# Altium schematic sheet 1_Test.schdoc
size 431 x 309 mm; Symbol: Sheet-Symbol_A3; Device: Sheet-Symbol_A3; Company: 嘉立创EDA; Version: V1.0; Page Size: A3; @Project Name: 辉光管_2024.2.16; @Page Count: 1; @Update Date: 2024-07-01; @Create Date: 2024-04-11; @Schematic Name: Schematic2; @Page No: 1; @Page Name: Test
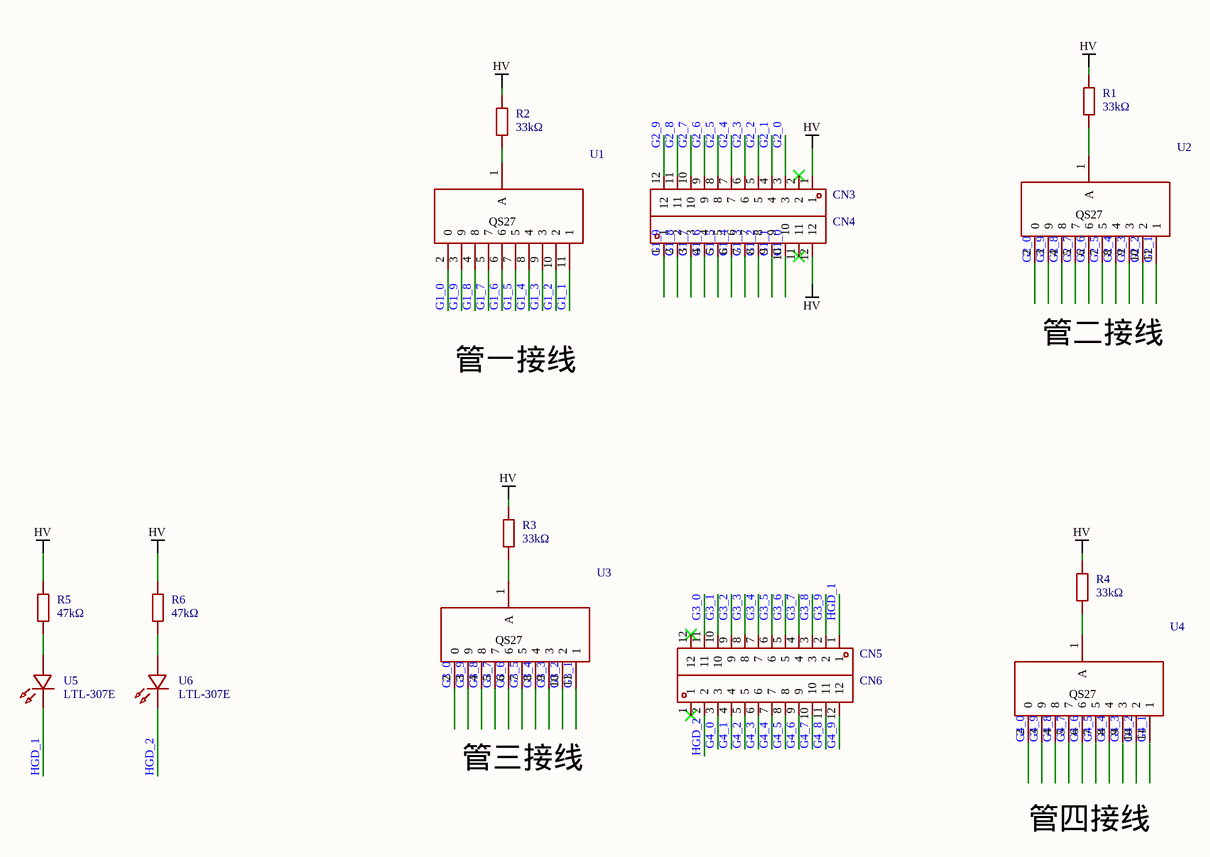
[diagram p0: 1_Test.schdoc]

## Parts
CN3  HB-PH3-254112PB2GOP  [HDR-TH_12P-P2.54-V-M]  (value not drawn)
CN4  HB-PH3-254112PB2GOP  [HDR-TH_12P-P2.54-V-M]  (value not drawn)
CN5  HB-PH3-254112PB2GOP  [HDR-TH_12P-P2.54-V-M]  (value not drawn)
CN6  HB-PH3-254112PB2GOP  [HDR-TH_12P-P2.54-V-M]  (value not drawn)
R1  33kΩ  [R0805]  (value not drawn)
R2  33kΩ  [R0805]  (value not drawn)
R3  33kΩ  [R0805]  (value not drawn)
R4  33kΩ  [R0805]  (value not drawn)
R5  47kΩ  [R0805]  (value not drawn)
R6  47kΩ  [R0805]  (value not drawn)
U1  QS27.1  [QS27]  (value not drawn)
U2  QS27.1  [QS27]  (value not drawn)
U3  QS27.1  [QS27]  (value not drawn)
U4  QS27.1  [QS27]  (value not drawn)
U5  LTL-307E  [LED-TH_BD5.9-P2.54-RD_RED]  (value not drawn)
U6  LTL-307E  [LED-TH_BD5.9-P2.54-RD_RED]  (value not drawn)

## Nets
HV: CN3.1 CN4.12 R1.2 R2.2 R3.2 R4.2 R5.2 R6.2
G1_0: CN4.10 U1.2(0)
G1_1: CN4.9 U1.11(1)
G1_2: CN4.8 U1.10(2)
G1_3: CN4.7 U1.9(3)
G1_4: CN4.6 U1.8(4)
G1_5: CN4.5 U1.7(5)
G1_6: CN4.4 U1.6
G1_7: CN4.3 U1.5(7)
G1_8: CN4.2 U1.4(8)
G1_9: CN4.1 U1.3(9)
G2_0: CN3.3 U2.2(0)
G2_1: CN3.4 U2.11(1)
G2_2: CN3.5 U2.10(2)
G2_3: CN3.6 U2.9(3)
G2_4: CN3.7 U2.8(4)
G2_5: CN3.8 U2.7(5)
G2_6: CN3.9 U2.6
G2_7: CN3.10 U2.5(7)
G2_8: CN3.11 U2.4(8)
G2_9: CN3.12 U2.3(9)
G3_0: CN5.11 U3.2(0)
G3_1: CN5.10 U3.11(1)
G3_2: CN5.9 U3.10(2)
G3_3: CN5.8 U3.9(3)
G3_4: CN5.7 U3.8(4)
G3_5: CN5.6 U3.7(5)
G3_6: CN5.5 U3.6
G3_7: CN5.4 U3.5(7)
G3_8: CN5.3 U3.4(8)
G3_9: CN5.2 U3.3(9)
G4_0: CN6.3 U4.2(0)
G4_1: CN6.4 U4.11(1)
G4_2: CN6.5 U4.10(2)
G4_3: CN6.6 U4.9(3)
G4_4: CN6.7 U4.8(4)
G4_5: CN6.8 U4.7(5)
G4_6: CN6.9 U4.6
G4_7: CN6.10 U4.5(7)
G4_8: CN6.11 U4.4(8)
G4_9: CN6.12 U4.3(9)
HGD_1: CN5.1 U5.1(C)
HGD_2: CN6.2 U6.1(C)
NetR1_1: R1.1 U2.1(A)
NetR2_1: R2.1 U1.1(A)
NetR3_1: R3.1 U3.1(A)
NetR4_1: R4.1 U4.1(A)
NetR5_1: R5.1 U5.2(A)
NetR6_1: R6.1 U6.2(A)

Not connected (* = marked no-connect by the designer): CN3 2*; CN4 11*; CN5 12*; CN6 1*

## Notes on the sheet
- 管二接线
- 管一接线
- 管三接线
- 管四接线

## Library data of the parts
CN3-CN6 = HB-PH3-254112PB2GOP: 插针结构:1x12P;间距:2.54mm;行距:2.54mm;圆针/方针:方针;安装类型:直插;排数:单排;总PIN位数:12P;额定电流:3A;额定电压:250V;配合针长度:6mm;塑高:2.54mm;端接针长度:3mm;触头材质:黄铜;触头镀层:金;工作温度范围:-40℃~+105℃;焊接温度(最大值):260℃;颜色:黑色;; Manufacturer: HANBO(汉博); Add into BOM: yes; Pin Structure: 1x12P; Pitch: 2.54mm; Circluar Pins/Square Pins: 方针; Current Rating (Max): 3A; Voltage Rating (Max): 250V; Soldering Temperature(Max): 260℃
R1-R4 = 0805W8F3302T5E: 电阻类型:厚膜电阻;阻值:33kΩ;精度:±1%;功率:125mW;最大工作电压:150V;温度系数:±100ppm/℃;; Manufacturer: UNI-ROYAL(厚声); Add into BOM: yes; Tolerance: ±1%; Power(Watts): 125mW; Overload Voltage (Max): 150V
R5 R6 = 0805W8F4702T5E: 电阻类型:厚膜电阻;阻值:47kΩ;精度:±1%;功率:125mW;最大工作电压:150V;温度系数:±100ppm/℃;; Manufacturer: UNI-ROYAL(厚声); Add into BOM: yes; Tolerance: ±1%; Power(Watts): 125mW; Overload Voltage (Max): 150V
U1-U4 = QS27.1: Add into BOM: yes
U5 U6 = LTL-307E: 发光颜色:红色;正向电压(VF):2V;正向电流:20mA;主波长:623nm;透镜颜色:红色透镜;发光强度:19mcd;发光角度:50°;; Manufacturer: LITEON(光宝); Add into BOM: yes; Emitted Color: 红色; Forward Voltage (VF): 2V; Forward Current: 20mA; Dominant Wavelength: 623nm; Peak Wavelength: 635nm; Lens Color: 红色透镜; Luminous Intensity: 19mcd; Viewing Angle: 50°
